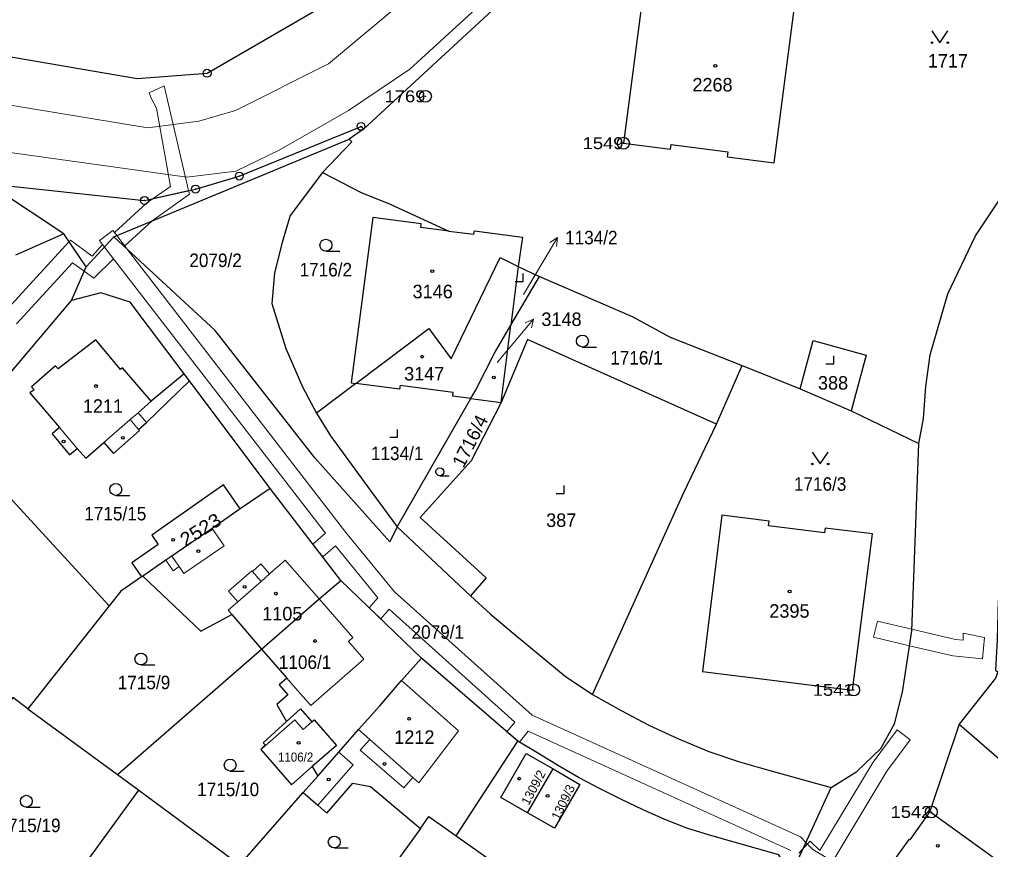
# Model space of a CAD drawing. Extents: x -679733 to -673243, y -1075091 to -1066557.
# Drawn here: x -676868.5 to -676746.3, y -1071850.5 to -1071746 of the extents above; entities that cross this region are included whole.
import ezdxf
from ezdxf.enums import TextEntityAlignment as Align

# ---------------------------------------------------------------- set-up
doc = ezdxf.new("R2010")
doc.units = 0
doc.header["$LTSCALE"] = 0.68
for name, color, linetype, lineweight in [('1', 7, 'Continuous', 25), ('13', 7, 'Continuous', 13), ('3', 7, 'Continuous', 25), ('4', 7, 'Continuous', 13), ('5', 7, 'Continuous', 25), ('7', 7, 'Continuous', 13), ('8', 7, 'Continuous', 25)]:
    doc.layers.add(name, color=color, linetype=linetype, lineweight=lineweight)
doc.layers.add('2', color=7, linetype='Continuous')

msp = doc.modelspace()

# ---------------------------------------------------------------- linework, layer by layer
at = {"layer": '1'}
for p, q in [((-676825.22, -1071759.86), (-676827.02, -1071761.13)), ((-676862.96, -1071773.03), (-676872.2, -1071766.9)), ((-676862.96, -1071773.03), (-676869.01, -1071775.7)), ((-676876.64, -1071798.73), (-676861.98, -1071781.43)), ((-676807.9, -1071794.25), (-676806.7, -1071784.54)), ((-676780.82, -1071796.99), (-676777.6, -1071789.6)), ((-676847.15, -1071791.53), (-676847.81, -1071790.66)), ((-676837, -1071805.08), (-676847.15, -1071791.53)), ((-676770.27, -1071792.52), (-676763.88, -1071795.29)), ((-676821, -1071809.91), (-676811.75, -1071793.75)), ((-676811.75, -1071793.75), (-676807.9, -1071794.25)), ((-676876.64, -1071798.73), (-676857.22, -1071819.86)), ((-676821, -1071809.91), (-676811.78, -1071818.6)), ((-676817.95, -1071826.46), (-676828.1, -1071816.65)), ((-676856.2, -1071841.09), (-676838.05, -1071825.29)), ((-676750.3, -1071834.75), (-676753.96, -1071845.75)), ((-676838.14, -1071837.94), (-676834.3, -1071842.37)), ((-676834.3, -1071842.37), (-676831.68, -1071840.08)), ((-676830.99, -1071841.28), (-676832.82, -1071843.36)), ((-676840.79, -1071852.44), (-676832.82, -1071843.36)), ((-676771.45, -1071853.79), (-676766.4, -1071842.71)), ((-676818.08, -1071847.87), (-676827.91, -1071861.55))]:
    msp.add_line(p, q, dxfattribs=at)
for points in [[(-676751.12, -1071692.06), (-676777.6, -1071716.31), (-676788.46, -1071725.85), (-676825.22, -1071759.86)], [(-677008.25, -1071788.41), (-676995.25, -1071771.16), (-676987.7, -1071761.27), (-676980.12, -1071752.62), (-676972.27, -1071748.26), (-676964.86, -1071744.84), (-676950.01, -1071743.35), (-676935.78, -1071742.14), (-676921.36, -1071742.37), (-676911.47, -1071742.59), (-676889.65, -1071747.32), (-676853.71, -1071753.48), (-676844.92, -1071752.82), (-676823.69, -1071740.46)], [(-676755.36, -1071799.42), (-676754.79, -1071796.28), (-676754.47, -1071792.26), (-676753.92, -1071788.28), (-676751.72, -1071780.58), (-676748.21, -1071773.29), (-676741.58, -1071763.33), (-676737.2, -1071756.59), (-676733.02, -1071749.38), (-676731.47, -1071746.17), (-676730.54, -1071744.07)], [(-676872.2, -1071766.9), (-676869.55, -1071767.02), (-676852.79, -1071768.83), (-676846.37, -1071767.4), (-676840.86, -1071765.76), (-676825.55, -1071759.5), (-676825.22, -1071759.86)], [(-676821, -1071809.91), (-676821.93, -1071811.81), (-676831.37, -1071801.24), (-676843.92, -1071785.19), (-676856.66, -1071773.41), (-676827.02, -1071761.13)], [(-676827.02, -1071761.13), (-676826.71, -1071761.46), (-676830.41, -1071765.32)], [(-676830.41, -1071765.32), (-676834.45, -1071770.74), (-676835.48, -1071774.13), (-676836.43, -1071777.94), (-676836.78, -1071781.79), (-676835.01, -1071787.45), (-676832.91, -1071792.27), (-676831.15, -1071795.62)], [(-676830.41, -1071765.32), (-676825.51, -1071767.83), (-676821.88, -1071769.29), (-676814.49, -1071772.68)], [(-676814.49, -1071772.68), (-676818.04, -1071772.22), (-676817.98, -1071771.78), (-676824.08, -1071770.98), (-676826.78, -1071791.79), (-676826.18, -1071791.87)], [(-676814.49, -1071772.68), (-676811.34, -1071773.09), (-676811.28, -1071772.64), (-676805.21, -1071773.43), (-676805.78, -1071777.13)], [(-676861.98, -1071781.43), (-676860.12, -1071777.17), (-676862.96, -1071773.03)], [(-676826.18, -1071791.87), (-676817, -1071784.94), (-676814.22, -1071788.75), (-676808.04, -1071776.02), (-676805.78, -1071777.13)], [(-676805.78, -1071777.13), (-676806.7, -1071784.54), (-676803.09, -1071778.39)], [(-676805.78, -1071777.13), (-676804.01, -1071778), (-676803.09, -1071778.39)], [(-676803.09, -1071778.39), (-676797.91, -1071780.61), (-676791.43, -1071783.43), (-676786.63, -1071786.04), (-676777.6, -1071789.6), (-676770.27, -1071792.52)], [(-676847.81, -1071790.66), (-676854.58, -1071781.62), (-676858.3, -1071780.47), (-676861.98, -1071781.43)], [(-676811.75, -1071793.75), (-676811.15, -1071792.73), (-676808.76, -1071788.06), (-676806.7, -1071784.54)], [(-676847.81, -1071790.66), (-676851.94, -1071794.09), (-676855.55, -1071789.89), (-676855.8, -1071790.1), (-676858.93, -1071786.38), (-676863.65, -1071790.02), (-676863.98, -1071789.63), (-676867.03, -1071792.27), (-676866.69, -1071792.66), (-676867.23, -1071793.04), (-676863.49, -1071797.42), (-676864.43, -1071798.22), (-676862.21, -1071800.84), (-676861.25, -1071800.03), (-676860.19, -1071801.27), (-676857.9, -1071799.28), (-676856.7, -1071800.66), (-676853.41, -1071797.79), (-676853.54, -1071797.67), (-676852.53, -1071796.79), (-676847.15, -1071791.53)], [(-676780.82, -1071796.99), (-676804.59, -1071786.32), (-676807.9, -1071794.25)], [(-676770.27, -1071792.52), (-676768.64, -1071786.45), (-676761.98, -1071788.32), (-676763.88, -1071795.29), (-676755.36, -1071799.42)], [(-676811.75, -1071793.75), (-676814, -1071793.46), (-676813.94, -1071793.01), (-676820.64, -1071792.13), (-676820.7, -1071792.58), (-676826.18, -1071791.87), (-676831.15, -1071795.62)], [(-676807.9, -1071794.25), (-676811.69, -1071801.6), (-676818.09, -1071808.75), (-676809.79, -1071816.32), (-676811.78, -1071818.6)], [(-676831.15, -1071795.62), (-676829.37, -1071798.47), (-676824.41, -1071805.3), (-676821, -1071809.91)], [(-676796.43, -1071831.02), (-676784.92, -1071805.6), (-676780.82, -1071796.99)], [(-676766.4, -1071842.71), (-676763.17, -1071840.7), (-676760.15, -1071837.83), (-676758.43, -1071834.69), (-676757.4, -1071830.7), (-676756.23, -1071822.99), (-676755.36, -1071799.42)], [(-676840.74, -1071807.66), (-676842.84, -1071804.63), (-676851.88, -1071810.97), (-676851.06, -1071812.14), (-676854.37, -1071814.46), (-676853.16, -1071816.22), (-676853, -1071816.11)], [(-676838.05, -1071825.29), (-676830.83, -1071818.96), (-676828.1, -1071816.65), (-676837, -1071805.08), (-676840.74, -1071807.66)], [(-676840.74, -1071807.66), (-676844.29, -1071810.11), (-676849.36, -1071813.6), (-676850.11, -1071814.12), (-676853, -1071816.11)], [(-676853.16, -1071816.22), (-676855.77, -1071818.02), (-676857.22, -1071819.86)], [(-676853, -1071816.11), (-676845.7, -1071823.03), (-676841.81, -1071820.94), (-676838.05, -1071825.29)], [(-676811.78, -1071818.6), (-676809.29, -1071820.87), (-676806.14, -1071823.5), (-676799.85, -1071828.71), (-676796.43, -1071831.02)], [(-676857.22, -1071819.86), (-676867.46, -1071832.8), (-676856.2, -1071841.09)], [(-676745.36, -1071819.18), (-676745.52, -1071824.15), (-676745.73, -1071827.94), (-676745.4, -1071828.18), (-676745.72, -1071828.95), (-676750.3, -1071834.75)], [(-676838.05, -1071825.29), (-676834.88, -1071828.97), (-676835.84, -1071829.78), (-676834.76, -1071831.05), (-676836.15, -1071832.28), (-676834.92, -1071834.42)], [(-676830.99, -1071841.28), (-676828.36, -1071838.28), (-676825.87, -1071835.43), (-676823.17, -1071832.44), (-676820.47, -1071829.26), (-676817.95, -1071826.46)], [(-676818.08, -1071847.87), (-676817.01, -1071846.38), (-676813.57, -1071848.81), (-676805.82, -1071836.89), (-676817.95, -1071826.46)], [(-676796.43, -1071831.02), (-676792.83, -1071833.03), (-676789.32, -1071834.89), (-676785.61, -1071836.61), (-676781.79, -1071838.2), (-676777.93, -1071839.51), (-676774.12, -1071840.58), (-676766.4, -1071842.71)], [(-676867.46, -1071832.8), (-676869.37, -1071831.39), (-676878.33, -1071844.13)], [(-676834.92, -1071834.42), (-676833.18, -1071832.83), (-676831.73, -1071834.47), (-676831.44, -1071834.22), (-676828.63, -1071837.43)], [(-676834.92, -1071834.42), (-676837.84, -1071837.09), (-676837.59, -1071837.37), (-676837.97, -1071837.72), (-676837.93, -1071837.76), (-676838.14, -1071837.94)], [(-676750.3, -1071834.75), (-676731.46, -1071851.09), (-676722.53, -1071858.73), (-676713.91, -1071849.04)], [(-676828.63, -1071837.43), (-676831.68, -1071840.08), (-676830.99, -1071841.28)], [(-676771.45, -1071853.79), (-676772.98, -1071851.21), (-676781.69, -1071848.73), (-676784.55, -1071847.83), (-676787.33, -1071846.73), (-676790.03, -1071845.53), (-676792.76, -1071844.24), (-676795.46, -1071842.89), (-676798.1, -1071841.51), (-676800.68, -1071840.01), (-676803.21, -1071838.43), (-676805.82, -1071836.89)], [(-676804.59, -1071845.91), (-676807.95, -1071843.96), (-676804.75, -1071838.43), (-676801.39, -1071840.38)], [(-676856.2, -1071841.09), (-676853.52, -1071843.07), (-676840.79, -1071852.44)], [(-676832.82, -1071843.36), (-676830.99, -1071844.96), (-676829.87, -1071845.95), (-676826.56, -1071842.18), (-676824.36, -1071842.61), (-676818.08, -1071847.87)], [(-676890.49, -1071861.28), (-676874.88, -1071872.43), (-676853.52, -1071843.07)], [(-676753.96, -1071845.75), (-676756.51, -1071849.32), (-676756.6, -1071849.26), (-676758.53, -1071851.97), (-676758.44, -1071852.04), (-676761.36, -1071856.12), (-676763.82, -1071859.59), (-676765.5, -1071862.03)], [(-676753.96, -1071845.75), (-676746.28, -1071851.3), (-676735, -1071859.62), (-676732.5, -1071862.87)], [(-676813.57, -1071848.81), (-676800.96, -1071857.74), (-676796.88, -1071860.63)]]:
    msp.add_lwpolyline(points, dxfattribs=at)
for points in [[(-676773.55, -1071764.09), (-676771, -1071744.47), (-676776.92, -1071743.7), (-676777, -1071744.29), (-676784.12, -1071743.37), (-676784.04, -1071742.77), (-676789.95, -1071742.01), (-676792.53, -1071761.62), (-676786.59, -1071762.39), (-676786.52, -1071761.79), (-676779.4, -1071762.72), (-676779.47, -1071763.32)], [(-676782.58, -1071828.1), (-676763.72, -1071830.45), (-676761.17, -1071810.81), (-676767.16, -1071810.06), (-676767.23, -1071810.66), (-676774.26, -1071809.78), (-676774.19, -1071809.19), (-676780.13, -1071808.45)], [(-676801.39, -1071840.38), (-676798.02, -1071842.33), (-676801.22, -1071847.86), (-676804.59, -1071845.91)]]:
    msp.add_lwpolyline(points, close=True, dxfattribs=at)
at = {"layer": '13'}
for points in [[(-676851.94, -1071755.97), (-676851.27, -1071757.21), (-676849.53, -1071767.08), (-676851.7, -1071768.59), (-676847.24, -1071767.59), (-676850.3, -1071754.41), (-676852.22, -1071755.29)], [(-676856.58, -1071772.87), (-676856.29, -1071773.25), (-676855.61, -1071774.14), (-676855.28, -1071774.56), (-676851.84, -1071771.41), (-676847.14, -1071768.03), (-676847.24, -1071767.59), (-676851.7, -1071768.59), (-676852.55, -1071769.18)], [(-676747.36, -1071826.51), (-676747.1, -1071823.86), (-676749.79, -1071823.28), (-676749.77, -1071824.17), (-676750.74, -1071824.08), (-676756.22, -1071822.79), (-676760.55, -1071821.78), (-676761.06, -1071823.81), (-676756.52, -1071824.87), (-676751.08, -1071826.14)]]:
    msp.add_lwpolyline(points, close=True, dxfattribs=at)
for points in [[(-676762.2, -1071854.44), (-676768.7, -1071850.51), (-676769.56, -1071849.64), (-676770.26, -1071848.93), (-676804.02, -1071833.61), (-676821.35, -1071818.08), (-676827.47, -1071810.63), (-676854.96, -1071774.98), (-676855.61, -1071774.14), (-676856.29, -1071773.25), (-676856.77, -1071772.62), (-676858.45, -1071773.88), (-676857.27, -1071775.44), (-676830, -1071810.69), (-676831.61, -1071812.09), (-676830.37, -1071813.7), (-676828.76, -1071812.3), (-676823.44, -1071818.84), (-676824.54, -1071820.09), (-676823.07, -1071821.51), (-676821.99, -1071820.27), (-676806.19, -1071834.49), (-676807.19, -1071835.72), (-676805.82, -1071836.89), (-676805.62, -1071837.01), (-676804.52, -1071835.65), (-676771.46, -1071850.65)], [(-676868.9, -1071784.36), (-676861.84, -1071776.66), (-676860.37, -1071777.74), (-676859.18, -1071778.62), (-676856.7, -1071776.18), (-676857.27, -1071775.44), (-676858.06, -1071774.39), (-676859.38, -1071775.84), (-676862.12, -1071773.82), (-676862.29, -1071774.01), (-676870.46, -1071782.94)], [(-676766.67, -1071852.84), (-676759.39, -1071840.68), (-676756.43, -1071836.72), (-676758.07, -1071835.48), (-676761.11, -1071839.54), (-676767.81, -1071850.66), (-676769.05, -1071849.49), (-676769.9, -1071850.39), (-676770.45, -1071850.97)]]:
    msp.add_lwpolyline(points, dxfattribs=at)
at = {"layer": '3'}
for p, q in [((-676829.973, -1071775.21), (-676828.223, -1071775.21)), ((-676797.683, -1071787.28), (-676795.933, -1071787.28)), ((-676815.625, -1071803.49), (-676814.453, -1071803.49)), ((-676856.403, -1071805.95), (-676854.653, -1071805.95)), ((-676853.243, -1071827.3), (-676851.493, -1071827.3)), ((-676842.013, -1071840.65), (-676840.263, -1071840.65)), ((-676867.663, -1071845.2), (-676865.913, -1071845.2)), ((-676828.913, -1071850.33), (-676827.163, -1071850.33))]:
    msp.add_line(p, q, dxfattribs=at)
for points in [[(-676753.71, -1071747.479), (-676752.71, -1071748.98), (-676751.71, -1071747.479)], [(-676806.131, -1071779.02), (-676805.13, -1071779.02), (-676805.13, -1071778.02)], [(-676767.051, -1071789.39), (-676766.05, -1071789.39), (-676766.05, -1071788.39)], [(-676821.941, -1071798.64), (-676820.94, -1071798.64), (-676820.94, -1071797.64)], [(-676768.76, -1071800.499), (-676767.76, -1071802), (-676766.76, -1071800.499)], [(-676800.981, -1071805.71), (-676799.98, -1071805.71), (-676799.98, -1071804.71)]]:
    msp.add_lwpolyline(points, dxfattribs=at)
for centre, radius in [((-676753.71, -1071748.9795), 0.1), ((-676751.71, -1071748.9795), 0.1), ((-676829.9729, -1071774.4598), 0.75), ((-676797.6829, -1071786.5298), 0.75), ((-676768.76, -1071801.9995), 0.1), ((-676766.76, -1071801.9995), 0.1), ((-676815.6252, -1071802.9874), 0.5025), ((-676856.4029, -1071805.1998), 0.75), ((-676853.2429, -1071826.5498), 0.75), ((-676842.0129, -1071839.8998), 0.75), ((-676867.6629, -1071844.4498), 0.75), ((-676828.9129, -1071849.5798), 0.75)]:
    msp.add_circle(centre, radius, dxfattribs=at)
at = {"layer": '4'}
for p, q in [((-676752.15, -1071690.71), (-676819.39, -1071752.3)), ((-676829.64, -1071751.64), (-676819.69, -1071743.29)), ((-676841.34, -1071757.49), (-676829.64, -1071751.64)), ((-676819.39, -1071752.3), (-676827.13, -1071757.51)), ((-676852.36, -1071759.69), (-676889.94, -1071753.53)), ((-676841.34, -1071757.49), (-676845.96, -1071758.84)), ((-676827.13, -1071757.51), (-676835.85, -1071762.49)), ((-676845.96, -1071758.84), (-676852.36, -1071759.69)), ((-676871.99, -1071762.48), (-676847.45, -1071765.89)), ((-676835.85, -1071762.49), (-676841.32, -1071765.16)), ((-676847.45, -1071765.89), (-676841.32, -1071765.16)), ((-676860.12, -1071777.17), (-676856.66, -1071773.41)), ((-676851.94, -1071794.09), (-676853.61, -1071795.54)), ((-676853.61, -1071795.54), (-676854.61, -1071796.41)), ((-676853.61, -1071795.54), (-676852.53, -1071796.79)), ((-676854.61, -1071796.41), (-676857.9, -1071799.28)), ((-676854.61, -1071796.41), (-676853.54, -1071797.67)), ((-676861.25, -1071800.03), (-676863.49, -1071797.42)), ((-676844.29, -1071810.11), (-676842.78, -1071812.3)), ((-676842.78, -1071812.3), (-676847.85, -1071815.8)), ((-676849.2, -1071815.44), (-676850.11, -1071814.12)), ((-676849.36, -1071813.6), (-676848.45, -1071814.92)), ((-676837.05, -1071815.82), (-676835.09, -1071814.09)), ((-676835.09, -1071814.09), (-676830.83, -1071818.96)), ((-676848.45, -1071814.92), (-676849.2, -1071815.44)), ((-676847.85, -1071815.8), (-676848.45, -1071814.92)), ((-676842.24, -1071818), (-676839.3, -1071815.44)), ((-676839.3, -1071815.44), (-676839.22, -1071815.53)), ((-676839.22, -1071815.53), (-676838.14, -1071814.58)), ((-676838.14, -1071814.58), (-676837.05, -1071815.82)), ((-676839.22, -1071815.53), (-676838.12, -1071816.77)), ((-676838.12, -1071816.77), (-676837.05, -1071815.82)), ((-676838.12, -1071816.77), (-676841.06, -1071819.37)), ((-676841.06, -1071819.37), (-676842.24, -1071818)), ((-676830.83, -1071818.96), (-676826.56, -1071823.83)), ((-676842.26, -1071820.41), (-676841.06, -1071819.37)), ((-676841.81, -1071820.94), (-676842.26, -1071820.41)), ((-676827.12, -1071824.34), (-676826.56, -1071823.83)), ((-676825.19, -1071826.58), (-676827.12, -1071824.34)), ((-676831.88, -1071832.38), (-676825.19, -1071826.58)), ((-676834.88, -1071828.97), (-676833.81, -1071830.21)), ((-676820.47, -1071829.26), (-676813.3, -1071835.57)), ((-676833.81, -1071830.21), (-676831.88, -1071832.38)), ((-676833.89, -1071834.21), (-676837.93, -1071837.76)), ((-676832.81, -1071835.42), (-676833.89, -1071834.21)), ((-676831.73, -1071834.47), (-676832.81, -1071835.42)), ((-676824.44, -1071836.67), (-676825.87, -1071835.43)), ((-676813.3, -1071835.57), (-676818.26, -1071842.12)), ((-676825.64, -1071838.04), (-676824.44, -1071836.67)), ((-676824.44, -1071836.67), (-676819.01, -1071841.46)), ((-676828.36, -1071838.28), (-676826.53, -1071839.88)), ((-676820.16, -1071842.76), (-676825.64, -1071838.04)), ((-676826.53, -1071839.88), (-676830.99, -1071844.96)), ((-676819.01, -1071841.46), (-676820.16, -1071842.76)), ((-676818.26, -1071842.12), (-676819.01, -1071841.46))]:
    msp.add_line(p, q, dxfattribs=at)
at = {"layer": '5'}
for centre in [(-676780.9668, -1071751.8892), (-676816.5768, -1071777.7292), (-676817.8568, -1071788.4892), (-676808.8468, -1071791.1092), (-676858.8968, -1071792.1892), (-676862.9668, -1071799.1692), (-676855.5168, -1071798.7192), (-676849.1868, -1071811.5492), (-676846.0168, -1071812.9592), (-676840.1868, -1071817.4492), (-676771.6168, -1071818.0392), (-676836.2568, -1071818.3192), (-676831.3368, -1071824.2792), (-676819.4768, -1071834.0592), (-676833.3968, -1071837.0992), (-676822.5868, -1071839.7592), (-676829.6168, -1071841.7192), (-676805.6368, -1071841.6092), (-676802.0668, -1071843.7692), (-676752.9568, -1071850.0592)]:
    msp.add_circle(centre, 0.175, dxfattribs=at)
at = {"layer": '7'}
for p, q in [((-676800.844, -1071773.508), (-676801.789, -1071774.108)), ((-676803.851, -1071783.781), (-676804.878, -1071784.226))]:
    msp.add_line(p, q, dxfattribs=at)
for points in [[(-676805.1, -1071780.67), (-676802.39, -1071776.08), (-676800.844, -1071773.508), (-676800.931, -1071774.624)], [(-676808.42, -1071789.22), (-676805.78, -1071786.08), (-676803.851, -1071783.781), (-676804.111, -1071784.87)]]:
    msp.add_lwpolyline(points, dxfattribs=at)
at = {"layer": '8'}
for centre, radius in [((-676844.92, -1071752.8199), 0.5), ((-676844.92, -1071752.8199), 0.0303), ((-676817.45, -1071755.7198), 0.75), ((-676817.45, -1071755.7198), 0.03), ((-676825.55, -1071759.4999), 0.5), ((-676825.55, -1071759.4999), 0.0303), ((-676792.53, -1071761.6198), 0.75), ((-676792.53, -1071761.6198), 0.03), ((-676840.86, -1071765.7599), 0.5), ((-676840.86, -1071765.7599), 0.0303), ((-676846.37, -1071767.3999), 0.5), ((-676846.37, -1071767.3999), 0.0303), ((-676852.79, -1071768.8299), 0.5), ((-676852.79, -1071768.8299), 0.0303), ((-676763.57, -1071830.4298), 0.75), ((-676763.57, -1071830.4298), 0.03), ((-676753.78, -1071845.7998), 0.75), ((-676753.78, -1071845.7998), 0.03)]:
    msp.add_circle(centre, radius, dxfattribs=at)

# ---------------------------------------------------------------- texts
at = {"layer": '2'}
for s, p in [('1717', (-676754.23, -1071752.1)), ('2268', (-676783.85, -1071755.11)), ('3146', (-676819.06, -1071781.14)), ('3148', (-676802.85, -1071784.63)), ('3147', (-676820.13, -1071791.489)), ('388', (-676768.05, -1071792.64)), ('1211', (-676860.55, -1071795.56)), ('387', (-676802.25, -1071809.92)), ('1105', (-676837.98, -1071821.69)), ('2395', (-676774.17, -1071821.35)), ('1212', (-676821.37, -1071837.229))]:
    msp.add_text(s, height=1.7, dxfattribs=at).set_placement(p)
at = {"layer": '2', "width": 0.95}
for s, height, p in [('1134/2', 1.7, (-676799.87, -1071774.35)), ('2079/2', 1.7, (-676847.15, -1071777.21)), ('1716/2', 1.7, (-676833.28, -1071778.39)), ('1716/1', 1.7, (-676794.19, -1071789.479)), ('1134/1', 1.7, (-676824.3, -1071801.509)), ('1716/3', 1.7, (-676771.08, -1071805.37)), ('1715/15', 1.7, (-676860.37, -1071809.1)), ('2079/1', 1.7, (-676819.19, -1071823.999)), ('1106/1', 1.7, (-676835.89, -1071827.8)), ('1715/9', 1.7, (-676856.16, -1071830.35)), ('1106/2', 1.14, (-676835.99, -1071839.459)), ('1715/10', 1.7, (-676846.17, -1071843.81)), ('1715/19', 1.7, (-676871.16, -1071848.34))]:
    msp.add_text(s, height=height, dxfattribs=at).set_placement(p)
at = {"layer": '2'}
for s, height, rotation, p in [('1716/4', 1.7, 63, (-676812.652, -1071802.595)), ('1309/2', 1.14, 62, (-676804.446, -1071845.047)), ('1309/3', 1.14, 64, (-676800.627, -1071846.909))]:
    msp.add_text(s, height=height, rotation=rotation, dxfattribs=at).set_placement(p)
at = {"layer": '2', "width": 1.1}
msp.add_text('2523', height=1.7, rotation=32, dxfattribs=at).set_placement((-676847.649, -1071812.46))
at = {"layer": '8', "width": 1.15}
for s, p in [('1769', (-676817.449, -1071756.47)), ('1549', (-676792.529, -1071762.37)), ('1541', (-676763.569, -1071831.179)), ('1542', (-676753.779, -1071846.55))]:
    msp.add_text(s, height=1.5, dxfattribs=at).set_placement(p, align=Align.RIGHT)

doc.saveas('drawing.dxf')
